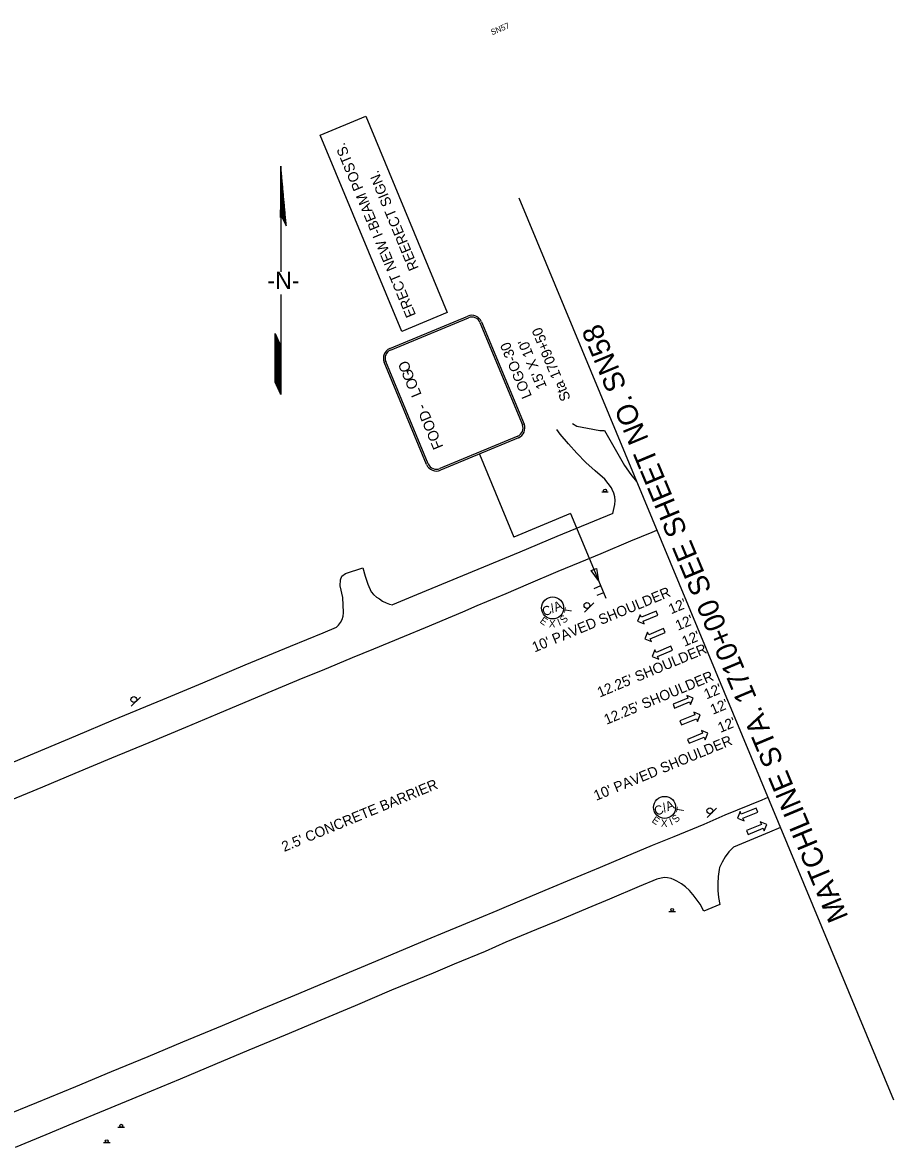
# Model space of a CAD drawing. Extents: x 1816080 to 1817753, y 1191002 to 1192408.
# Drawn here: x 1817158 to 1817753, y 1191640 to 1192408 of the extents above; entities that cross this region are included whole.
import ezdxf

# ---------------------------------------------------------------- set-up
doc = ezdxf.new("R2010")
doc.units = 0
for name, color, linetype in [('RD_EX_Road', 7, 'Continuous'), ('RD_PD_Final_LnLine', 7, 'Continuous'), ('RD_PD_Final_TX', 7, 'Continuous'), ('RD_SHT_MatchLine', 7, 'Continuous'), ('RD_SHT_TX', 7, 'Continuous'), ('RD_Sketch1', 7, 'Continuous'), ('RD_Sketch8', 7, 'Continuous'), ('SN_P_Signs', 7, 'Continuous')]:
    doc.layers.add(name, color=color, linetype=linetype)

# ---------------------------------------------------------------- blocks, each defined once
blk = doc.blocks.new('SARRW2')
at = {"layer": 'RD_PD_Final_LnLine'}
blk.add_lwpolyline([(-12, 1.2), (-12, -1.2), (-2.83, -1.2), (-2.83, -2.83), (0, 0), (-2.83, 2.83), (-2.83, 1.2)], close=True, dxfattribs=at)

msp = doc.modelspace()

# ---------------------------------------------------------------- linework, layer by layer
at = {"layer": 'RD_EX_Road'}
for points in [[(1817533.93, 1192134.32), (1817536.85, 1192132.65), (1817544.24, 1192131.31), (1817552.53, 1192129.71), (1817555.69, 1192129.61), (1817569.41, 1192105.68), (1817573.81, 1192099.58), (1817577.66, 1192094.8)], [(1817561.35, 1192073.04), (1817562.86, 1192079.18), (1817563, 1192081.81), (1817562.75, 1192084.43), (1817562.11, 1192086.98), (1817561.09, 1192089.41), (1817560.44, 1192090.58), (1817556.04, 1192096.45), (1817549.39, 1192102.03), (1817543.01, 1192107.91), (1817536.9, 1192114.07), (1817531.08, 1192120.5), (1817525.55, 1192127.19), (1817523.16, 1192130.36)], [(1817561.35, 1192073.04), (1817523.15, 1192057.2), (1817497.97, 1192046.67), (1817458.88, 1192030.56), (1817427.46, 1192017.45), (1817410.96, 1192010.69)], [(1817147.59, 1191876.11), (1817172.24, 1191886.42), (1817194.45, 1191895.79), (1817219.49, 1191906.26), (1817244.88, 1191916.79), (1817269.91, 1191927.19), (1817291.64, 1191936.34), (1817314.88, 1191946.07), (1817350.09, 1191960.74), (1817363.23, 1191966.16), (1817383.78, 1191974.65), (1817398.23, 1191980.68), (1817419.21, 1191989.25), (1817433.51, 1191995.22), (1817459.11, 1192005.99), (1817468.87, 1192010.11), (1817488.65, 1192018.46), (1817503.91, 1192024.96), (1817524.17, 1192033.65), (1817539.22, 1192039.83), (1817553.45, 1192045.69), (1817573.79, 1192054.33), (1817588.25, 1192060.36), (1817591.4, 1192061.72)], [(1817372.53, 1191995.15), (1817374.19, 1191996.75), (1817375.56, 1191998.6), (1817376.59, 1192000.66), (1817377.26, 1192002.87), (1817377.54, 1192005.15), (1817377.54, 1192005.43), (1817377.19, 1192015.57), (1817375.37, 1192023.66), (1817375.56, 1192027.81), (1817376.54, 1192030.32), (1817378.89, 1192031.94), (1817390.82, 1192035.81), (1817392.3, 1192030.28), (1817394.15, 1192024.86), (1817396.37, 1192019.58), (1817396.39, 1192019.53), (1817398.07, 1192017.62), (1817400.03, 1192015.98), (1817402.21, 1192014.67), (1817402.22, 1192014.66), (1817404.31, 1192013.12), (1817406.62, 1192011.92), (1817409.07, 1192011.07), (1817410.96, 1192010.69)], [(1817372.53, 1191995.15), (1817363.39, 1191991.25), (1817341.13, 1191982.19), (1817310.28, 1191969.45), (1817281.38, 1191957.26), (1817253.92, 1191945.78), (1817220.39, 1191931.94), (1817194.55, 1191921.05), (1817159.28, 1191906.27), (1817133.62, 1191895.47)], [(1817667.28, 1191879.14), (1817663.07, 1191877.4), (1817637.84, 1191867.01), (1817623.45, 1191860.85), (1817603.05, 1191852.42), (1817588.3, 1191846.36), (1817569.44, 1191838.37), (1817552.77, 1191831.4), (1817532.89, 1191823.18), (1817517.8, 1191816.74), (1817497.67, 1191808.34), (1817482.33, 1191801.89), (1817458.2, 1191791.85), (1817446.64, 1191786.95), (1817434.51, 1191781.96), (1817399.48, 1191767.37), (1817374.42, 1191756.83), (1817346.83, 1191745.3), (1817320, 1191733.96), (1817294.7, 1191723.38), (1817267.77, 1191712.26), (1817243.99, 1191702.27), (1817219.02, 1191691.92), (1817194.64, 1191681.8), (1817167.93, 1191670.92), (1817144.65, 1191661.34)], [(1817675.81, 1191858.62), (1817668.46, 1191855.57), (1817643.78, 1191845.32), (1817640.94, 1191842.4), (1817640.62, 1191842.02), (1817638.18, 1191838.68), (1817636.06, 1191835.12), (1817634.3, 1191831.38), (1817634.04, 1191830.06), (1817633.34, 1191825.31), (1817633.05, 1191820.52), (1817633.14, 1191815.72), (1817633.63, 1191810.94), (1817634.51, 1191806.22), (1817623.59, 1191801.57), (1817620.96, 1191806.48), (1817616.27, 1191812.7), (1817616.03, 1191813.01), (1817613.72, 1191815.7), (1817611.12, 1191818.11), (1817608.27, 1191820.21), (1817605.21, 1191821.99), (1817603.4, 1191823.04), (1817601.15, 1191823.93), (1817598.79, 1191824.44), (1817596.38, 1191824.56), (1817591.57, 1191823.47), (1817579.32, 1191818.38), (1817559.09, 1191809.86), (1817544.31, 1191803.63), (1817523.84, 1191795.09), (1817509.43, 1191789.08), (1817488.47, 1191780.36), (1817474.2, 1191774.16), (1817453.1, 1191765.38), (1817438.74, 1191759.39), (1817410.39, 1191747.59), (1817385.61, 1191737.03), (1817362.18, 1191727.13), (1817337.79, 1191716.95), (1817312.92, 1191706.64), (1817289.84, 1191697.06), (1817266.04, 1191686.98), (1817239.74, 1191676.14), (1817214.99, 1191665.85), (1817192.73, 1191656.6), (1817174.36, 1191649.05), (1817153.46, 1191640.32)]]:
    msp.add_lwpolyline(points, dxfattribs=at)
at = {"layer": 'RD_SHT_MatchLine'}
msp.add_line((1817497.17, 1192288.47), (1817753.03, 1191672.81), dxfattribs=at)
at = {"layer": 'RD_Sketch1'}
for p, q in [((1817334.83, 1192310.1), (1817334.62, 1192274.93)), ((1817338.55, 1192269.4), (1817334.83, 1192310.1)), ((1817334.83, 1192275.23), (1817334.83, 1192253.41)), ((1817335.13, 1192276.34), (1817338.55, 1192269.4)), ((1817334.83, 1192253.41), (1817334.83, 1192237.93)), ((1817334.83, 1192222.49), (1817334.83, 1192196.71)), ((1817330.84, 1192181.66), (1817330.84, 1192195.83)), ((1817330.84, 1192195.83), (1817334.83, 1192187.26)), ((1817334.83, 1192196.71), (1817334.83, 1192154.19)), ((1817330.84, 1192162.76), (1817330.84, 1192181.66)), ((1817334.83, 1192154.19), (1817330.84, 1192162.76))]:
    msp.add_line(p, q, dxfattribs=at)
for points in [[(1817334.84, 1192275.54), (1817334.84, 1192309.98)], [(1817334.94, 1192275.8), (1817334.94, 1192308.95)], [(1817335.03, 1192276.06), (1817335.03, 1192307.91)], [(1817335.12, 1192276.32), (1817335.12, 1192306.88)], [(1817335.22, 1192276.16), (1817335.22, 1192305.85)], [(1817335.31, 1192275.97), (1817335.31, 1192304.82)], [(1817335.41, 1192275.78), (1817335.41, 1192303.78)], [(1817335.5, 1192275.59), (1817335.5, 1192302.75)], [(1817334.75, 1192275.28), (1817334.75, 1192296.06)], [(1817335.6, 1192275.4), (1817335.6, 1192301.72)], [(1817335.69, 1192275.21), (1817335.69, 1192300.69)], [(1817335.79, 1192275.01), (1817335.79, 1192299.65)], [(1817335.88, 1192274.82), (1817335.88, 1192298.62)], [(1817335.97, 1192274.63), (1817335.97, 1192297.59)], [(1817336.07, 1192274.44), (1817336.07, 1192296.56)], [(1817336.16, 1192274.25), (1817336.16, 1192295.52)], [(1817336.26, 1192274.06), (1817336.26, 1192294.49)], [(1817336.35, 1192273.86), (1817336.35, 1192293.46)], [(1817336.45, 1192273.67), (1817336.45, 1192292.43)], [(1817336.54, 1192273.48), (1817336.54, 1192291.39)], [(1817336.64, 1192273.29), (1817336.64, 1192290.36)], [(1817336.73, 1192273.1), (1817336.73, 1192289.33)], [(1817336.82, 1192272.91), (1817336.82, 1192288.3)], [(1817336.92, 1192272.71), (1817336.92, 1192287.26)], [(1817334.65, 1192275.02), (1817334.65, 1192280.16)], [(1817337.01, 1192272.52), (1817337.01, 1192286.23)], [(1817337.11, 1192272.33), (1817337.11, 1192285.2)], [(1817337.2, 1192272.14), (1817337.2, 1192284.17)], [(1817337.3, 1192271.95), (1817337.3, 1192283.13)], [(1817337.39, 1192271.76), (1817337.39, 1192282.1)], [(1817337.49, 1192271.56), (1817337.49, 1192281.07)], [(1817337.58, 1192271.37), (1817337.58, 1192280.04)], [(1817337.68, 1192271.18), (1817337.68, 1192279)], [(1817337.77, 1192270.99), (1817337.77, 1192277.97)], [(1817337.86, 1192270.8), (1817337.86, 1192276.94)], [(1817337.96, 1192270.6), (1817337.96, 1192275.91)], [(1817338.05, 1192270.41), (1817338.05, 1192274.87)], [(1817338.15, 1192270.22), (1817338.15, 1192273.84)], [(1817338.24, 1192270.03), (1817338.24, 1192272.81)], [(1817338.34, 1192269.84), (1817338.34, 1192271.78)], [(1817338.43, 1192269.65), (1817338.43, 1192270.74)], [(1817338.53, 1192269.45), (1817338.53, 1192269.71)], [(1817330.91, 1192162.59), (1817330.91, 1192195.66)], [(1817331.01, 1192162.39), (1817331.01, 1192195.46)], [(1817331.1, 1192162.19), (1817331.1, 1192195.26)], [(1817331.2, 1192161.98), (1817331.2, 1192195.06)], [(1817331.29, 1192161.78), (1817331.29, 1192194.85)], [(1817331.39, 1192161.58), (1817331.39, 1192194.65)], [(1817331.48, 1192161.38), (1817331.48, 1192194.45)], [(1817331.57, 1192161.17), (1817331.57, 1192194.24)], [(1817331.67, 1192160.97), (1817331.67, 1192194.04)], [(1817331.76, 1192160.77), (1817331.76, 1192193.84)], [(1817331.86, 1192160.57), (1817331.86, 1192193.64)], [(1817331.95, 1192160.36), (1817331.95, 1192193.43)], [(1817332.05, 1192160.16), (1817332.05, 1192193.23)], [(1817332.14, 1192159.96), (1817332.14, 1192193.03)], [(1817332.24, 1192159.76), (1817332.24, 1192192.83)], [(1817332.33, 1192159.55), (1817332.33, 1192192.62)], [(1817332.43, 1192159.35), (1817332.43, 1192192.42)], [(1817332.52, 1192159.15), (1817332.52, 1192192.22)], [(1817332.61, 1192158.95), (1817332.61, 1192192.02)], [(1817332.71, 1192158.74), (1817332.71, 1192191.81)], [(1817332.8, 1192158.54), (1817332.8, 1192191.61)], [(1817332.9, 1192158.34), (1817332.9, 1192191.41)], [(1817332.99, 1192158.13), (1817332.99, 1192191.21)], [(1817333.09, 1192157.93), (1817333.09, 1192191)], [(1817333.18, 1192157.73), (1817333.18, 1192190.8)], [(1817333.28, 1192157.53), (1817333.28, 1192190.6)], [(1817333.37, 1192157.32), (1817333.37, 1192190.39)], [(1817333.46, 1192157.12), (1817333.46, 1192190.19)], [(1817333.56, 1192156.92), (1817333.56, 1192189.99)], [(1817333.65, 1192156.72), (1817333.65, 1192189.79)], [(1817333.75, 1192156.51), (1817333.75, 1192189.58)], [(1817333.84, 1192156.31), (1817333.84, 1192189.38)], [(1817333.94, 1192156.11), (1817333.94, 1192189.18)], [(1817334.03, 1192155.91), (1817334.03, 1192188.98)], [(1817334.13, 1192155.7), (1817334.13, 1192188.77)], [(1817334.22, 1192155.5), (1817334.22, 1192188.57)], [(1817334.31, 1192155.3), (1817334.31, 1192188.37)], [(1817334.41, 1192155.1), (1817334.41, 1192188.17)], [(1817334.5, 1192154.89), (1817334.5, 1192187.96)], [(1817334.6, 1192154.69), (1817334.6, 1192187.76)], [(1817334.69, 1192154.49), (1817334.69, 1192187.56)], [(1817334.79, 1192154.28), (1817334.79, 1192187.36)]]:
    msp.add_lwpolyline(points, dxfattribs=at)
at = {"layer": 'RD_Sketch8'}
for centre in [(1817520.34, 1192008.54), (1817596.79, 1191872.42)]:
    msp.add_circle(centre, 7.5, dxfattribs=at)
at = {"layer": 'SN_P_Signs'}
for p, q in [((1817361.7, 1192331.22), (1817392.74, 1192344.12)), ((1817392.74, 1192344.12), (1817448.39, 1192210.21)), ((1817417.35, 1192197.31), (1817361.7, 1192331.22)), ((1817448.39, 1192210.21), (1817417.35, 1192197.31)), ((1817470.35, 1192113.57), (1817493.88, 1192056.95)), ((1817553.83, 1192087.68), (1817558.33, 1192087.68)), ((1817532.56, 1192073.03), (1817493.88, 1192056.95)), ((1817532.56, 1192073.03), (1817551.6, 1192027.2)), ((1817551.6, 1192027.2), (1817556.61, 1192015.16)), ((1817553.1, 1192023.59), (1817548.49, 1192021.68)), ((1817555.03, 1192018.96), (1817550.42, 1192017.04)), ((1817542, 1192005.62), (1817548.36, 1192011.99)), ((1817232.7, 1191941.4), (1817239.07, 1191947.76)), ((1817625.89, 1191865.49), (1817632.25, 1191871.85)), ((1817599.71, 1191801.42), (1817604.21, 1191801.42)), ((1817223.59, 1191654.13), (1817228.09, 1191654.13)), ((1817213.71, 1191643.64), (1817218.21, 1191643.64))]:
    msp.add_line(p, q, dxfattribs=at)
for points in [[(1817409.22, 1192185.62), (1817462.41, 1192207.73)], [(1817409.68, 1192184.51), (1817462.87, 1192206.62)], [(1817470.72, 1192203.38), (1817499.73, 1192133.57)], [(1817471.82, 1192203.84), (1817500.84, 1192134.03)], [(1817434.35, 1192106.4), (1817405.34, 1192176.21)], [(1817435.46, 1192106.86), (1817406.44, 1192176.67)], [(1817496.49, 1192125.73), (1817443.3, 1192103.62)], [(1817496.95, 1192124.62), (1817443.76, 1192102.51)]]:
    msp.add_lwpolyline(points, dxfattribs=at)
msp.add_lwpolyline([(1817550.35, 1192035.56), (1817551.6, 1192027.2), (1817546.56, 1192033.99)], close=True, dxfattribs=at)
for centre, radius in [((1817556.09, 1192088.69), 1), ((1817543.76, 1192010.25), 2), ((1817234.47, 1191946.02), 2), ((1817627.65, 1191870.11), 2), ((1817601.96, 1191802.44), 1), ((1817225.84, 1191655.15), 1), ((1817215.97, 1191644.65), 1)]:
    msp.add_circle(centre, radius, dxfattribs=at)
for centre, radius, start, end in [((1817465.17, 1192201.08), 7.2, 22.56659, 112.56659), ((1817465.17, 1192201.08), 6, 22.56659, 112.56659), ((1817411.98, 1192178.97), 7.2, 112.56659, 202.56659), ((1817411.98, 1192178.97), 6, 112.56659, 202.56659), ((1817494.19, 1192131.27), 7.2, 292.56659, 22.56659), ((1817494.19, 1192131.27), 6, 292.56659, 22.56659), ((1817441, 1192109.16), 7.2, 202.56659, 292.56659), ((1817441, 1192109.16), 6, 202.56659, 292.56659)]:
    msp.add_arc(centre, radius, start, end, dxfattribs=at)

# ---------------------------------------------------------------- block references
at = {"layer": 'RD_PD_Final_LnLine', "xscale": 1.2000000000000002}
for p, yscale, rotation in [((1817578.37, 1191999.51), 1.2000000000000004, -157.44760385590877), ((1817583.33, 1191987.57), 1.2000000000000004, -157.44760385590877), ((1817588.35, 1191975.49), 1.2000000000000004, -157.44760385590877), ((1817616.36, 1191947.02), 1.2000000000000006, 22.552396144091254), ((1817621.11, 1191935.59), 1.2000000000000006, 22.552396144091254), ((1817626.33, 1191923.03), 1.2000000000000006, 22.552396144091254), ((1817646.55, 1191865.09), 1.2000000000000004, -157.44760385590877), ((1817666.54, 1191860.83), 1.2000000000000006, 22.552396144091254)]:
    msp.add_blockref('SARRW2', p, dxfattribs=dict(at, yscale=yscale, rotation=rotation))

# ---------------------------------------------------------------- texts
at = {"layer": 'RD_PD_Final_TX'}
for s, rotation, p in [("10' PAVED SHOULDER", 22.4268, (1817508.03, 1191978.13)), ("12'", 22.75903, (1817601.22, 1192004.14)), ("12'", 22.75903, (1817605.87, 1191992.94)), ("12'", 22.75903, (1817610.4, 1191982.05)), ("12.25' SHOULDER", 22.56659, (1817552.55, 1191947.36)), ("12.25' SHOULDER", 22.56659, (1817557.16, 1191928.78)), ("12'", 22.75903, (1817625.36, 1191946.05)), ("12'", 22.75903, (1817629.71, 1191935.58)), ("12'", 22.75903, (1817634.85, 1191923.2)), ("10' PAVED SHOULDER", 22.4268, (1817550.11, 1191876.87)), ("2.5' CONCRETE BARRIER", 22.4268, (1817337.11, 1191842))]:
    msp.add_text(s, height=7, rotation=rotation, dxfattribs=at).set_placement(p)
at = {"layer": 'RD_SHT_TX'}
for s, height, rotation, p in [('SN57', 4, 22.56659, (1817479, 1192399.35)), ('MATCHLINE STA. 1710+00 SEE SHEET NO. SN58', 14.1726, 112.67894, (1817722.4, 1191797.69))]:
    msp.add_text(s, height=height, rotation=rotation, dxfattribs=at).set_placement(p)
at = {"layer": 'RD_Sketch1'}
msp.add_text('-N-', height=11.811, rotation=0, dxfattribs=at).set_placement((1817325.63, 1192226.2))
at = {"layer": 'RD_Sketch8'}
for s, height, rotation, p in [('C/A', 6.25, 22.56659, (1817514.76, 1192002.67)), ('S', 5, 44.35903, (1817528.12, 1191997.62)), ('T', 5, 80.75173, (1817533.1, 1192004.41)), ('E', 5, 325.77783, (1817511.18, 1191998.75)), ('X', 5, 358.2072, (1817517.76, 1191995.37)), ('I', 5, 22.3672, (1817524.82, 1191996.06)), ('C/A', 6.25, 22.56659, (1817591.2, 1191866.55)), ('T', 5, 80.75173, (1817609.54, 1191868.29)), ('E', 5, 325.77783, (1817587.62, 1191862.63)), ('I', 5, 22.3672, (1817601.26, 1191859.93)), ('S', 5, 44.35903, (1817604.57, 1191861.5)), ('X', 5, 358.2072, (1817594.2, 1191859.24))]:
    msp.add_text(s, height=height, rotation=rotation, dxfattribs=at).set_placement(p)
at = {"layer": 'SN_P_Signs'}
for s, height, rotation, p in [('ERECT NEW I-BEAM POSTS.', 6.9998, 112.56667, (1817427.18, 1192208.48)), ('REERECT SIGN.', 6.9998, 112.56667, (1817429.05, 1192240.45)), ('Sta 1709+50', 7, 112.56667, (1817532.79, 1192151.4)), ('LOGO-30', 7, 112.56667, (1817506.28, 1192153.16)), ("15' X 10'", 7, 112.56667, (1817516.51, 1192159.56)), ('O', 7.2, 112.56659, (1817424.03, 1192171.1)), ('G', 7.2, 112.56659, (1817426.4, 1192165.39)), ('O', 7.2, 112.56659, (1817428.86, 1192159.46)), ('L', 7.2, 112.56659, (1817431.07, 1192154.17)), ('FOOD', 7.2, 112.56659, (1817445.87, 1192118.54)), ('-', 7.2, 112.56659, (1817434.66, 1192145.51))]:
    msp.add_text(s, height=height, rotation=rotation, dxfattribs=at).set_placement(p)

doc.saveas('drawing.dxf')
